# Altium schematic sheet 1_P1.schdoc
size 307 x 218 mm; Symbol: Drawing-Symbol_A4; Device: Drawing-Symbol_A4; Company: 嘉立创EDA; Version: V1.0; Page Size: A4; @Project Name: New Project_2025-01-23_00-40-50; @Page Count: 1; @Update Date: 2025-08-16; @Create Date: 2025-07-17; @Schematic Name: Schematic5; @Page No: 1; @Page Name: P1; @Create Time: 23:49:42; @Update Time: 16:59:54; Width: 1170; Height: 825; Region Start: 1; X Region Count: 6; Y Region Count: 4; Blade Width: 10; Title Block Position: 3; @Board Name: stm32+uart
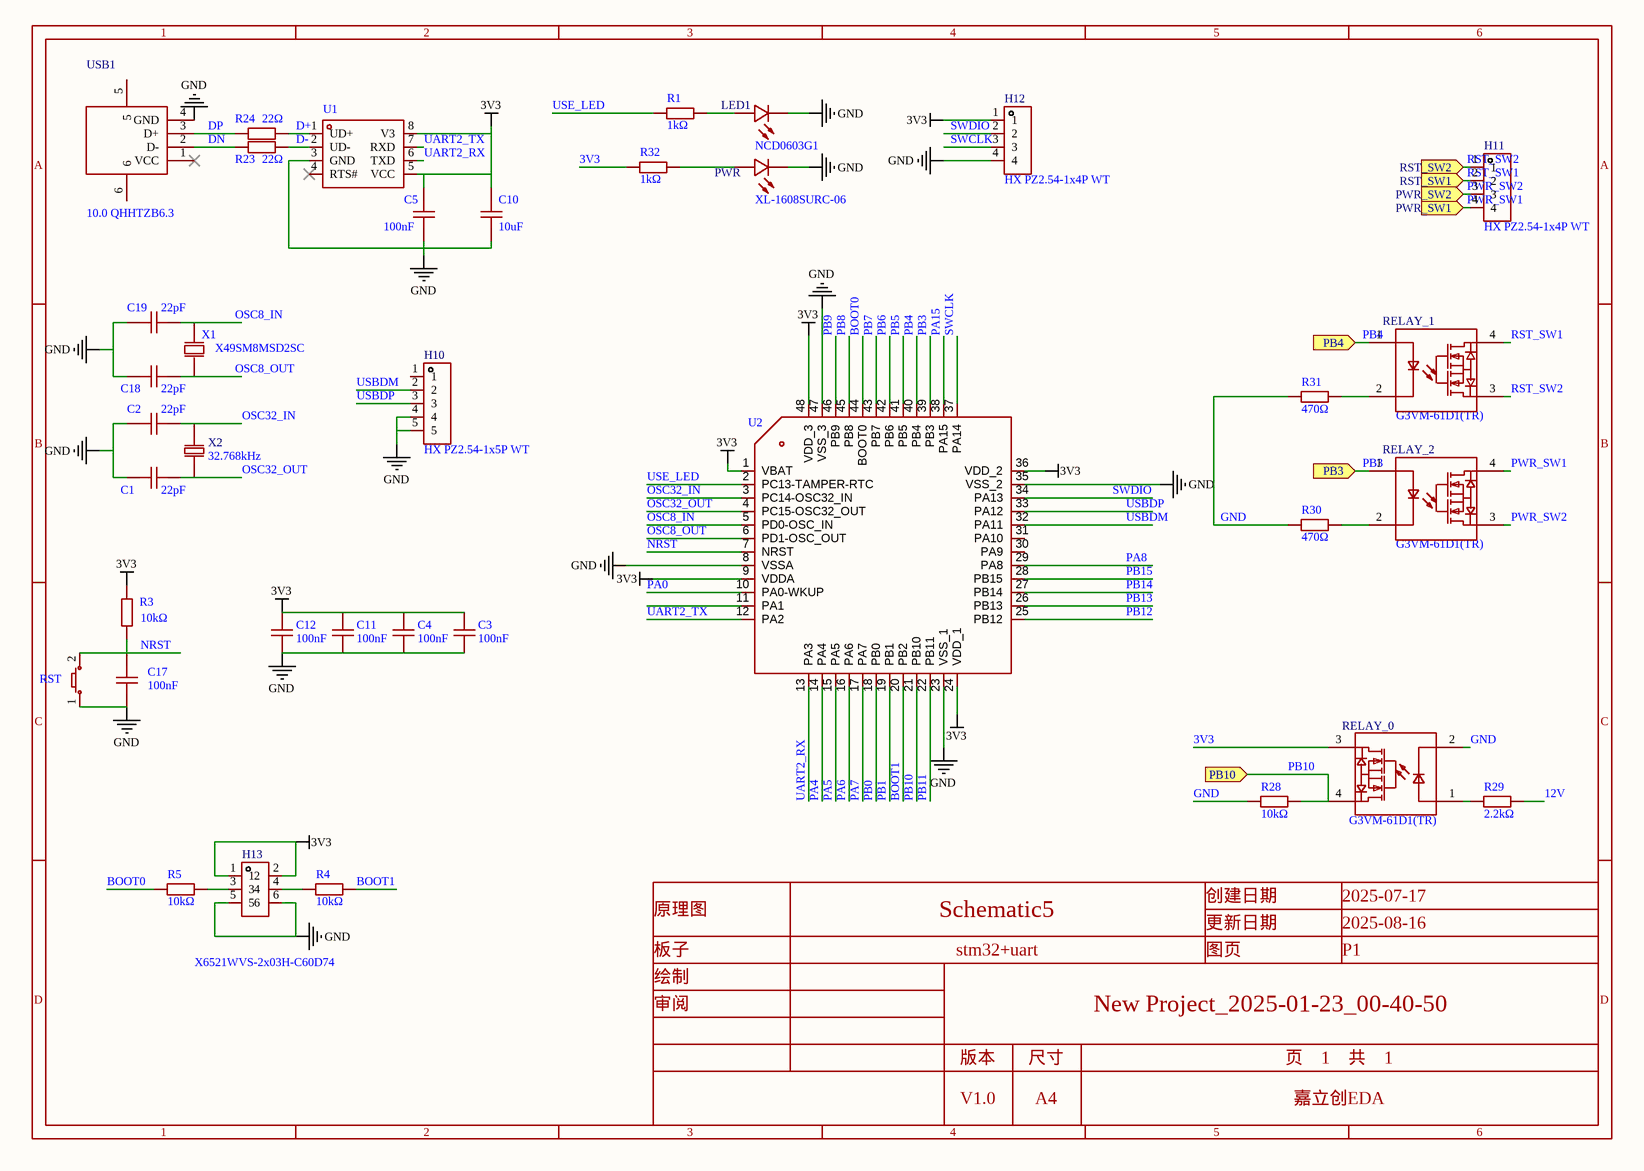
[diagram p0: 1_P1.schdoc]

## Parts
C1  22pF  [C0603]
C2  22pF  [C0603]
C3  100nF  [C0603]
C4  100nF  [C0603]
C5  100nF  [C0603]
C10  10uF  [C0805]
C11  100nF  [C0603]
C12  100nF  [C0603]
C17  100nF  [C0603]
C18  22pF  [C0603]
C19  22pF  [C0603]
H10  HX PZ2.54-1x5P WT  [HDR-SMD_5P-P2.54-H-M-W12.8-N]
H11  HX PZ2.54-1x4P WT  [CONN-SMD_HX-PZ2.54-1X4P-WT]
H12  HX PZ2.54-1x4P WT  [CONN-SMD_HX-PZ2.54-1X4P-WT]
H13  X6521WVS-2x03H-C60D74  [HDR-SMD_6P-P2.54-V-M-R2-C5-S7.4]
LED1  NCD0603G1  [LED0603-RD_1]
PWR  XL-1608SURC-06  [LED0603-RD_RED]
R1  1kΩ  [R0603]
R3  10kΩ  [R0603]
R4  10kΩ  [R0603]
R5  10kΩ  [R0603]
R23  22Ω  [R0603]
R24  22Ω  [R0603]
R28  10kΩ  [R0603]
R29  2.2kΩ  [R0603]
R30  470Ω  [R0603]
R31  470Ω  [R0603]
R32  1kΩ  [R0603]
RELAY_0  G3VM-61D1(TR)  [SMD-4_L4.6-W6.4-P2.54-LS10.0-BL]
RELAY_1  G3VM-61D1(TR)  [SMD-4_L4.6-W6.4-P2.54-LS10.0-BL]
RELAY_2  G3VM-61D1(TR)  [SMD-4_L4.6-W6.4-P2.54-LS10.0-BL]
RST  TS-1088-AR02016  [SW-SMD_L3.9-W3.0-P4.45]  (value not drawn)
U1  CH340N  [SOP-8_L5.0-W4.0-P1.27-LS6.0-BL]  (value not drawn)
U2  (no value)  [STM32F103C8T6]
USB1  10.0 QHHTZB6.3  [USB-A-TH_10.0QHHTZB6.3]
X1  8MHz  [CRYSTAL-SMD_L11.5-W4.8-LS12.7]  (value not drawn)
X2  32.768kHz  [FC-135R_L3.2-W1.5]

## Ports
PB3 (in), PB4 (in), PB10 (in), PWR_SW1 (in), PWR_SW2 (in), RST_SW1 (in), RST_SW2 (in)

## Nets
3V3: C3.2 C4.1 C5.2 C10.2 C11.1 C12.1 H12.1 H13.1 H13.2 R3.2 R32.1 RELAY_0.3 U1.5(VCC) U1.8(V3) U2.1(VBAT) U2.9(VDDA) U2.24(VDD_1) U2.36(VDD_2) U2.48(VDD_3)
GND: C1.1 C2.1 C3.1 C4.2 C5.1 C10.1 C11.2 C12.2 C17.1 C18.1 C19.1 H10.4 H10.5 H12.4 H13.5 H13.6 LED1.1(K) PWR.1(K) R28.1 R30.1 R31.1 RELAY_0.2 RST.1 U1.3(GND) U2.8(VSSA) U2.23(VSS_1) U2.35(VSS_2) U2.47(VSS_3) USB1.4(GND)
12V: R29.2
BOOT0: R5.2 U2.44(BOOT0)
BOOT1: R4.1 U2.20(PB2)
D+: R24.2 U1.1(UD+)
D-: R23.2 U1.2(UD-)
DN: R23.1 USB1.2(D-)
DP: R24.1 USB1.3(D+)
NRST: C17.2 R3.1 RST.2 U2.7(NRST)
OSC8_IN: C19.2 U2.5(PD0-OSC_IN) X1.2(OSC2)
OSC8_OUT: C18.2 U2.6(PD1-OSC_OUT) X1.1(OSC1)
OSC32_IN: C2.2 U2.3(PC14-OSC32_IN) X2.2
OSC32_OUT: C1.2 U2.4(PC15-OSC32_OUT) X2.1
PA0: U2.10(PA0-WKUP)
PA4: U2.14(PA4)
PA5: U2.15(PA5)
PA6: U2.16(PA6)
PA7: U2.17(PA7)
PA8: U2.29(PA8)
PA15: U2.38(PA15)
PB0: U2.18(PB0)
PB1: U2.19(PB1)
PB3: RELAY_2.1 U2.39(PB3) ; port PB3
PB4: RELAY_1.1 U2.40(PB4) ; port PB4
PB5: U2.41(PB5)
PB6: U2.42(PB6)
PB7: U2.43(PB7)
PB8: U2.45(PB8)
PB9: U2.46(PB9)
PB10: R28.2 RELAY_0.4 U2.21(PB10) ; port PB10
PB11: U2.22(PB11)
PB12: U2.25(PB12)
PB13: U2.26(PB13)
PB14: U2.27(PB14)
PB15: U2.28(PB15)
PWR_SW1: H11.4 RELAY_2.4 ; port PWR_SW1
PWR_SW2: H11.3 RELAY_2.3 ; port PWR_SW2
RST_SW1: H11.2 RELAY_1.4 ; port RST_SW1
RST_SW2: H11.1 RELAY_1.3 ; port RST_SW2
SWCLK: H12.3 U2.37(PA14)
SWDIO: H12.2 U2.34(PA13)
UART2_RX: U1.6(TXD) U2.13(PA3)
UART2_TX: U1.7(RXD) U2.12(PA2)
USBDM: H10.2 U2.32(PA11)
USBDP: H10.3 U2.33(PA12)
USE_LED: R1.1 U2.2(PC13-TAMPER-RTC)
NetH13_3: H13.3 R5.1
NetH13_4: H13.4 R4.2
NetLED1_2: LED1.2(A) R1.2
NetPWR_2: PWR.2(A) R32.2
NetR29_1: R29.1 RELAY_0.1
NetR30_2: R30.2 RELAY_2.2
NetR31_2: R31.2 RELAY_1.2

Not connected (* = marked no-connect by the designer): H10 1; U1 4(RTS#)*; U2 11(PA1) 30(PA9) 31(PA10); USB1 1(VCC)* 5 6

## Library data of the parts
C1 C2 C18 C19 = CL10C220JB8NNNC: Manufacturer: SAMSUNG(三星); Symbol: CapAcitance; Add into BOM: yes; Tolerance: ±5%; Voltage Rated: 50V; Temperature Coefficient: C0G
C3 C4 C11 C12 = CGA0603X7R104K500JT: Manufacturer: HRE(芯声); Symbol: CL21B104KBCNNNC; Add into BOM: yes; Tolerance: ±10%; Voltage Rating: 50V; Temperature Coefficient: X7R
C5 C17 = CGA0603X7R104K500JT: Manufacturer: HRE(芯声); Symbol: CapAcitance; Add into BOM: yes; Tolerance: ±10%; Voltage Rating: 50V; Temperature Coefficient: X7R
C10 = CL21A106KAYNNNE_C15850: Manufacturer: SAMSUNG(三星); Symbol: CapAcitance; Add into BOM: yes; Tolerance: ±10%; Voltage Rated: 25V; Temperature Coefficient: X5R
H10 = HX PZ2.54-1x5P WT: Manufacturer: hanxia(韩下); Add into BOM: yes; Pin Structure: 1x5P; Pitch: 2.54mm; Circluar Pins/Square Pins: 方针; Current Rating: 3A
H11 H12 = HX PZ2.54-1x4P WT: Manufacturer: hanxia(韩下); Add into BOM: yes; Pin Structure: 1x4P; Pitch: 2.54mm; Circluar Pins/Square Pins: 方针; Current Rating: 3A
H13 = X6521WVS-2x03H-C60D74: Manufacturer: XKB Connection(中国星坤); Symbol: X6521WVS-2*03H-C60D74; Add into BOM: yes; Pin Structure: 2x3P; Pitch: 2.54mm; Circluar Pins/Square Pins: 方针; Current Rating: 3A; Voltage Rating (Max): 250V
LED1 = NCD0603G1: Manufacturer: 国星光电; Symbol: FC-D1608UGK-520D10; Add into BOM: yes; Illumination Color: 翠绿色; Voltage - Forward(Vf): 2.6V~3.6V; Power(Watts): 72mW; Forward Current: 20mA; Wavelength - Dominant: 515nm~530nm; Luminous Intensity: 330mcd~900mcd; Viewing Angle: 130°
PWR = XL-1608SURC-06: Manufacturer: XINGLIGHT(成兴光); Symbol: FC-D1608UGK-520D10; Add into BOM: yes; Illumination Color: 红色; Voltage - Forward(Vf): 2.3V; Power(Watts): 50mW; Forward Current: 20mA; Wavelength - Dominant: 620nm~630nm; Peak Wavelength: 625nm; Lens Color: 无色透明透镜; Luminous Intensity: 225mcd; Viewing Angle: 120°; Mounting Sytle: 正贴
R1 R32 = 0603WAF1001T5E: Manufacturer: UNI-ROYAL(厚声); Symbol: 电阻; Add into BOM: yes; Tolerance: ±1%; Power(Watts): 100mW; Overload Voltage (Max): 75V; Temperature Coefficient: ±100ppm/℃
R3-R5 R28 = 0603WAF1002T5E: Manufacturer: UNI-ROYAL(厚声); Symbol: 电阻; Add into BOM: yes; Tolerance: ±1%; Power(Watts): 100mW; Voltage-Supply(Max): 75V; Temperature Coefficient: ±100ppm/℃
R23 R24 = 0603WAF220JT5E: Manufacturer: UNI-ROYAL(厚声); Symbol: 电阻; Add into BOM: yes; Tolerance: ±1%; Power(Watts): 100mW; Overload Voltage (Max): 75V; Temperature Coefficient: ±100ppm/℃
R29 = 0603WAF2201T5E: Manufacturer: UNI-ROYAL(厚声); Symbol: 电阻; Add into BOM: yes; Tolerance: ±1%; Power(Watts): 100mW; Overload Voltage (Max): 75V; Temperature Coefficient: ±100ppm/℃
R30 R31 = 0603WAF4700T5E: Manufacturer: UNI-ROYAL(厚声); Symbol: 电阻; Add into BOM: yes; Tolerance: ±1%; Power(Watts): 100mW; Overload Voltage (Max): 75V; Temperature Coefficient: ±100ppm/℃
RELAY_0-RELAY_2 = G3VM-61D1(TR): Manufacturer: OMRON(欧姆龙); Add into BOM: yes; Relay Contact Form: 1 Form A(SPST-NO); Load Type: AC,DC; Input Forward Voltage: 1.15V; Voltage - Load: 60V; Continuous Load Current: 500mA; On Resistance: 1Ω; Isolation Voltage(rms): 2.5kV; Turn-on time: 800us; Turn-off time: 100us
RST = TS-1088-AR02016: Manufacturer: XUNPU(讯普); Symbol: 轻触按键x2; Add into BOM: yes; Circuit: 单刀单掷; Actuator Style: 圆形按钮; Operating Force: 160gf; Switch Length: 4mm; Switch Width: 3mm; Switch Height: 2mm; Strike Gundam: 不带; Contact Current: 50mA; Voltage Rating (DC): 12V; Insulation Resistance: 100MΩ; Actuator/Cap Color: 黑色; Pin Style: SMD接片; Mechanical Life: 10万次
U1 = CH340N_C506813: Manufacturer: WCH(南京沁恒); Add into BOM: yes
U2 = STM32F103C8T6: Manufacturer: STMicroelectronics; Add into BOM: yes
USB1 = 10.0 QHHTZB6.3: Manufacturer: SHOU HAN(首韩); Add into BOM: yes; Connector Type: Type-A; Protocol Standard: USB 2.0; Gender: 母; Number of Contacts: 4P; Number of Ports: 1; Current Rating-Power: 1.5A; Voltage Rating: 30V; Connect-Disconnect Life: 5千次; Detection color: 黑色
X1 = X49SM8MSD2SC: Manufacturer: YXC(扬兴晶振); Symbol: 8MHZ_C9900021358; Add into BOM: yes; Normal temperature Frequency Tolerance: ±20ppm; Load Capacitance: 20pF; Frequency Stability: ±30ppm
X2 = Q13FC13500004_C32346: Manufacturer: EPSON(爱普生); Symbol: Q13FC1350000400; Add into BOM: yes; Crystal Type: 贴片晶振; Normal temperature Frequency Tolerance: ±20ppm; Load Capacitor: 12.5pF; Equivalent Series Resistance (ESR): 70kΩ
